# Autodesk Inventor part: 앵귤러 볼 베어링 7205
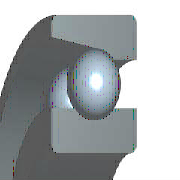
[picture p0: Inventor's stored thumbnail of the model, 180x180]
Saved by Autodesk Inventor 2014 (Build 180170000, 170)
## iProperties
Created: 2012-02
Part Number: 앵귤러 볼 베어링 7205
Material: 강철, 연강
Description: 앵귤러 콘택트 볼 베어링
Document SubType Name: Modeling
Standard: KS B 2024
Designer: mduedu
Standards Organization: KS
Language: ko-KR
Size Designation: 7205 - 25 x 52 x 15
Categories: <MemberInstance><Categories><Category DisplayName="샤프트 부품" InternalName="7f7aeb1f-a693-4053-b835-cee3144e0d98" Mnemonic="SHFT"><Category DisplayName="베어링" Inter
Density: 1 g/cm^3
Appearance: Yellow
IsCustomPart: 1
Author: mduedu
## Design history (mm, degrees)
sketch "스케치" dims "d1" = 7.02 (= -0.26 x WD + 0.26 x BD)
  geometry: L1 (3.99, 19.25)-(11.01, 19.25); L2 (7.5, 22.76)-(7.5, 15.74); L3 (0, 16.901)-(4.892, 16.901); L4 (0, 12.5)-(15, 12.5); L5 (8.11, 22.707)-(0, 24.137); L6 (15, 16.901)-(15, 12.5); L7 (15, 16.901)-(10.108, 16.901); L8 (15, 21.599)-(10.108, 21.599); L9 (15, 21.599)-(15, 26); L10 (0, 26)-(15, 26); L11 (-2.4, 0)-(14.4, 0) reference; L12 (0, -1.44)-(0, 8.99) reference; 1 further point
  constraints: 20 end point, 4 point on line, 3 symmetric about line, 2 midpoint, 2 parallel, 1 perpendicular, 14 other
  dimensions: "d0" = 10 deg angle of L8 L5; "d11" = 25 diameter of L4 L11 (= WD); "d12" = 52 diameter of L10 L11 (= BD); "d13" = 15 distance between parallel lines of L6 L12 (= KB); "d14" = 33.802 diameter of L7 L11 (= 0.326 x BD + 0.674 x WD)
revolve "본체" stored, may be unused: angle "d6" = 90 deg
revolve "볼" stored, may be unused: angle "d8" = 90 deg
pattern_circular "IDS_ARRAYBALL[SIMPL:T]" dims angle "d4" = 360 deg
body "Solid1"
fillet "모깎기1" dims "d2" = 1 (= KRS)
other parameters: "WD" = 25 [user parameter; used in 5 equation terms], "BD" = 52 [user parameter; used in 5 equation terms], "KB" = 15 [user parameter; used in 1 equation term], "KRS" = 1 [user parameter; used in 1 equation term], "d5" = 0, "d7" = 0, "d9" = 0, "d15" = 0, "d16" = 0, "BC0" = 1.02e+07 [user parameter], "BBA" = 30 deg [user parameter], "BC" = 1.56e+07 [user parameter], "KR1S" = 0.6 [user parameter], "BR" = 26 (= 0.5 x BD) [user parameter], "WR" = 12.5 (= 0.5 x WD) [user parameter]
